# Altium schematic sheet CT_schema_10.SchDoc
size 297 x 239 mm
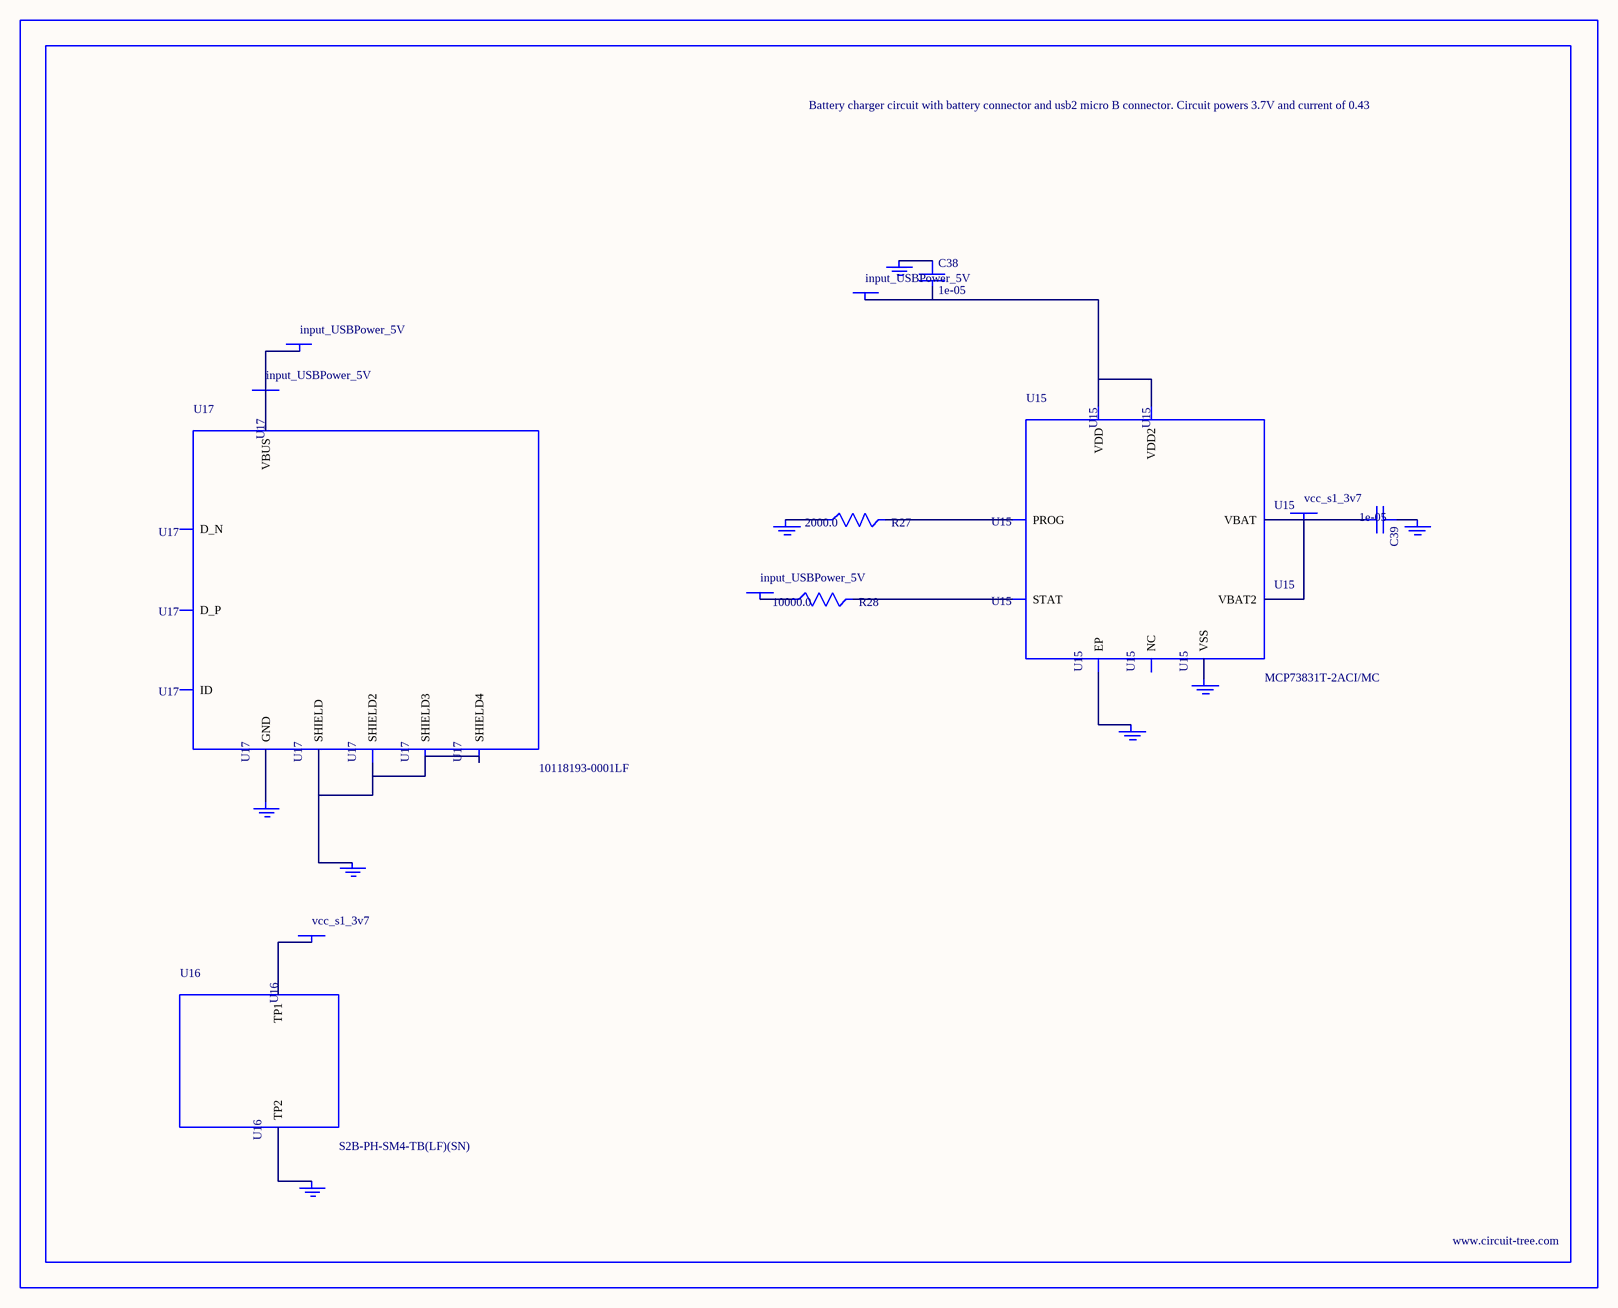
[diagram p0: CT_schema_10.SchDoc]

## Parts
BORDER9  (no value)
C38  1e-05  [C1206]
C39  1e-05  [C1206]
GND_INSTANCE_9_0  (no value)
GND_INSTANCE_9_1  (no value)
GND_INSTANCE_9_2  (no value)
GND_INSTANCE_9_3  (no value)
GND_INSTANCE_9_4  (no value)
GND_INSTANCE_9_5  (no value)
GND_INSTANCE_9_6  (no value)
GND_INSTANCE_9_7  (no value)
POWER_INSTANCE_9_0  input_USBPower_5V
POWER_INSTANCE_9_1  input_USBPower_5V
POWER_INSTANCE_9_2  vcc_s1_3v7
POWER_INSTANCE_9_3  vcc_s1_3v7
POWER_INSTANCE_9_4  input_USBPower_5V
POWER_INSTANCE_9_5  input_USBPower_5V
R27  2000.0  [R0603]
R28  10000.0  [R0603]
U15  MCP73831T-2ACI/MC  [DFN8_2X3MC]
U16  S2B-PH-SM4-TB(LF)(SN)  [JST-2-SMD]
U17  10118193-0001LF  [FCI_10118193-0001LF]

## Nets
NetC38_1: C38.1 GND_INSTANCE_9_0.0(GND)
NetC38_2: C38.2 POWER_INSTANCE_9_0.0(PWR) U15.1(VDD) U15.2(VDD2)
NetC39_1: C39.1 GND_INSTANCE_9_1.0(GND)
NetC39_2: C39.2 POWER_INSTANCE_9_2.0(PWR) U15.3(VBAT) U15.4(VBAT2)
NetGND_INSTANCE_9_2_0: GND_INSTANCE_9_2.0(GND) R27.1
NetGND_INSTANCE_9_3_0: GND_INSTANCE_9_3.0(GND) U15.9(EP)
NetGND_INSTANCE_9_4_0: GND_INSTANCE_9_4.0(GND) U15.6(VSS)
NetGND_INSTANCE_9_5_0: GND_INSTANCE_9_5.0(GND) U16.2(TP2)
NetGND_INSTANCE_9_6_0: GND_INSTANCE_9_6.0(GND) U17.6(SHIELD) U17.7(SHIELD2) U17.8(SHIELD3) U17.9(SHIELD4)
NetGND_INSTANCE_9_7_0: GND_INSTANCE_9_7.0(GND) U17.5(GND)
NetPOWER_INSTANCE_9_1_0: POWER_INSTANCE_9_1.0(PWR) R28.1
NetPOWER_INSTANCE_9_3_0: POWER_INSTANCE_9_3.0(PWR) U16.1(TP1)
NetPOWER_INSTANCE_9_4_0: POWER_INSTANCE_9_4.0(PWR) POWER_INSTANCE_9_5.0(PWR) U17.1(VBUS)
NetR27_2: R27.2 U15.8(PROG)
NetR28_2: R28.2 U15.5(STAT)

Not connected (* = marked no-connect by the designer): U15 7(NC); U17 2(D_N) 3(D_P) 4(ID)

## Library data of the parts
BORDER9 = BORDER_PAGE9
C38 C39 = C1206C106K3RACTU
GND_INSTANCE_9_0-GND_INSTANCE_9_7 = GND
POWER_INSTANCE_9_0-POWER_INSTANCE_9_5 = PWR
R27 = RC0603JR-072KL
R28 = RC0603JR-0710KL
